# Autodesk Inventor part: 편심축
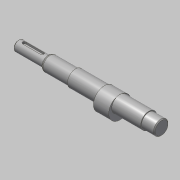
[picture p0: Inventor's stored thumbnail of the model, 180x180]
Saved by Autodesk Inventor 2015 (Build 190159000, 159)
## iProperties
Created: 2017-08
Part Number: 편심축
Material: 강철, 연강
Document SubType Name: Modeling
Designer: mduedu
Density: 7.86 g/cm^3
Appearance: 강철
Mass: 338.4 g
Surface Area: 105.4 cm^2
Volume: 43.0534 cm^3
Author: mduedu
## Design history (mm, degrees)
sketch "스케치1"
  geometry: L1 (0, 0)-(168, 0); L2 (168, 0)-(168, 8.5); L3 (168, 8.5)-(153, 8.5); L4 (153, 8.5)-(153, 9.5); L5 (153, 9.5)-(67, 9.5); L6 (67, 9.5)-(67, 8.5); L7 (67, 8.5)-(35, 8.5); L8 (35, 8.5)-(35, 6); L9 (35, 6)-(0, 6); L10 (0, 6)-(0, 0)
  constraints: 20 end point, 6 parallel, 2 collinear, 2 perpendicular, 1 horizontal
  dimensions: "d0" = 168 distance of L1.start L1.end; "d1" = 17 diameter of L3 L1; "d2" = 19 diameter of L5 L1; "d3" = 12 diameter of L9 L1; "d4" = 35 distance of L8.end L9.end; "d5" = 15 distance of L2.end L3.end; "d6" = 86 distance of L4.end L5.end
revolve "회전1" sketch "스케치1" stored, may be unused: angle "d7" = 90 deg
node "작업 평면1"
sketch "스케치2"
  geometry: C1 r 9.5 at (0, 0) reference; C2 r 13 at (0, -3.5); 1 further point
  constraints: 1 centre point, 1 tangent, 1 vertical alignment
  dimensions: "d8" = 3.5 distance of point (0, 0) C2.centre
extrude "돌출1" join sketch "스케치2" stored distance "d9" = 18; taper "d10" = 0 deg
chamfer "모따기1" distance "d11" = 1; stored, may be unused: second distance "d12" = 2, angle "d13" = 45 deg
node "작업 평면2"
sketch "스케치3"
  geometry: L1 (10.5, -2)-(-10.5, -2); L2 (-10.5, -2)-(-10.5, 2); L3 (-10.5, 2)-(10.5, 2); L4 (10.5, 2)-(10.5, -2); L5 (17.5, 6)-(17.5, -6) reference; L6 (-17.5, 8.5)-(-17.5, -8.5) reference; A1 r 2 centre (10.5, 0) between (10.5, -2) and (10.5, 2); A2 r 2 centre (-10.5, 0) between (-10.5, 2) and (-10.5, -2); A3 r 2 centre (10.5, 0) between (10.5, 2) and (10.5, -2); A4 r 2 centre (-10.5, 0) between (-10.5, -2) and (-10.5, 2); 1 further point
  constraints: 8 end point, 8 point on circle, 4 centre point, 2 midpoint, 2 parallel, 1 horizontal, 1 horizontal alignment, 1 perpendicular
  dimensions: "d14" = 25 dimension on A2 A1; "d16" = 4 distance between parallel lines of L3 L1; "d17" = 5 distance edge to line of A1 L5; "d46" = 5 distance edge to line of A2 L6 (derived)
extrude "돌출2" cut sketch "스케치3" distance "d18" = 2.5; taper "d19" = 0 deg
chamfer "모따기2" distance "d20" = 1; stored, may be unused: second distance "d21" = 2, angle "d22" = 45 deg
chamfer "모따기4" distance "d39" = 1.82; stored, may be unused: second distance "d40" = 2, angle "d41" = 30 deg
fillet "모깎기4" dims "d45" = 2
hole "구멍1" diameter "d29" = 3.242; stored, may be unused: countersink angle "d33" = 90 deg, drill point angle "d35" = 118 deg; dims "d30" = 8, "d31" = 4, "d32" = 2, "d34" = 10, "d36" = 10, "d37" = 10
node "솔리드1"
node "절단 모서리 투영1"
